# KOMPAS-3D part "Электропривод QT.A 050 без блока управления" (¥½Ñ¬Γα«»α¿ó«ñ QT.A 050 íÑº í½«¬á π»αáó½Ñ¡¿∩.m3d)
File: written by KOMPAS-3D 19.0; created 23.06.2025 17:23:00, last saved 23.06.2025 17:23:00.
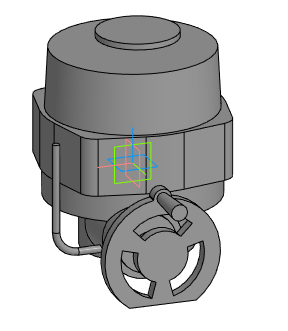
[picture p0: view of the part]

Document properties: Автор: Евгений; Полное имя файла: E:\Dendor Работа Сачек\3D для проектировщиков\3.5 Тип QT.А Электропривод\stp_Электропривод QT.A без блока управления\Электропривод QT.A 050 без блока управления.m3d

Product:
- Part/product: Электропривод QT.A 050 без блока управления

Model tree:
1. Операция без истории:1  (labels: Электропривод QT.A 050 без блока управления)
